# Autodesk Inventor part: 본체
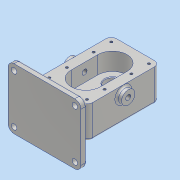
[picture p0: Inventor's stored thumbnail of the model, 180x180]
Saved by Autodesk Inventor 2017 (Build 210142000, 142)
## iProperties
Part Number: 본체
Material: 알루미늄 6061
Document SubType Name: Modeling
Designer: MRC
Density: 2.7 g/cm^3
Appearance: 알루미늄 - 평지
Mass: 1475.56 g
Surface Area: 817.688 cm^2
Volume: 546.504 cm^3
Author: MRC
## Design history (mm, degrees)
sketch "스케치1"
  geometry: L1 (40, -60)-(-40, -60); L2 (-40, -60)-(-40, 60); L3 (-40, 60)-(40, 60); L4 (40, 60)-(40, -60); L5 (40, -60)-(-40, 60); L6 (-40, -60)-(40, 60); 1 further point
  constraints: 12 end point, 2 midpoint, 2 parallel, 1 horizontal, 1 perpendicular
  dimensions: "d0" = 80 distance of L2.end L3.end; "d1" = 120 distance of L1.end L2.end
extrude "돌출1" new body sketch "스케치1" distance "d2" = 14; taper "d4" = 0 deg; dims "d3" = 39, "d5" = 0
sketch "스케치2"
  geometry: L1 (0, 22)-(0, -22); L2 (-24, 22)-(-24, -22); L3 (24, -22)-(24, 22); A1 r 24 centre (0, 22) between (24, 22) and (-24, 22); A2 r 24 centre (0, -22) between (-24, -22) and (24, -22); 2 further points
  constraints: 8 end point, 4 point on circle, 4 tangent, 2 centre point, 2 coincident, 1 midpoint, 1 parallel, 1 vertical
  dimensions: "d6" = 24 radius of A1; "d7" = 92 dimension on A1 A2
extrude "돌출2" cut sketch "스케치2" distance "d8" = 29; taper "d9" = 0 deg
sketch "스케치3"
  geometry: C1 r 12.5 at (0, 22); C2 r 12.5 at (0, -22); A1 r 24 centre (0, -22) between (-24, -22) and (24, -22) reference; A2 r 24 centre (0, 22) between (24, 22) and (-24, 22) reference; 1 further point
  constraints: 2 centre point, 2 coincident
  dimensions: "d10" = 25 diameter of C1; "d11" = 25 diameter of C2
extrude "돌출3" cut sketch "스케치3" distance "d12" = 15; taper "d13" = 0 deg
sketch "스케치4"
  geometry: C1 r 19 at (0, 22); C2 r 12.5 at (0, 22) reference; 1 further point
  constraints: 1 centre point, 1 concentric
  dimensions: "d14" = 38 diameter of C1
extrude "돌출4" join sketch "스케치4" distance "d15" = 17; taper "d16" = 0 deg
hole "구멍1" diameter "d19" = 17; stored, may be unused: countersink angle "d23" = 90 deg, drill point angle "d25" = 118 deg; dims "d17" = 10, "d18" = 10, "d20" = 6, "d21" = 28, "d22" = 7.3, "d24" = 8
sketch "스케치5"
  geometry: L1 (40, -60)-(40, 60) reference; L2 (-31, 51)-(31, 51); L3 (31, 51)-(31, 22); L4 (31, 22)-(31, -22); L5 (31, -22)-(31, -51); L6 (31, -51)-(-31, -51); L7 (-31, -51)-(-31, -22); L8 (-31, -22)-(-31, 22); L9 (-31, 22)-(-31, 51); A1 r 24 centre (0, 22) between (24, 22) and (-24, 22) reference; 3 further points
  constraints: 16 end point, 3 perpendicular, 3 vertical alignment, 2 midpoint, 2 parallel, 1 collinear, 1 horizontal alignment, 1 vertical
  dimensions: "d26" = 102 distance of L6.end L2.start; "d27" = 44 distance of L7.end L8.end; "d28" = 29 distance of L2.start L8.end; "d99" = 29 distance of L2.end L3.end; "d100" = 44 distance of L3.end L4.end; "d101" = 62 distance of L2.end L2.start
hole "구멍2" sketch "스케치5" at (-31, 51), (-31, 22), (-31, -22), (-31, -51), (31, -51), (31, -22), (31, 22), (31, 51) diameter "d29" = 4.134; stored, may be unused: countersink angle "d33" = 90 deg, drill point angle "d35" = 118 deg; dims "d30" = 10, "d31" = 28, "d32" = 7.3, "d34" = 12
sketch "스케치6"
  geometry: C1 r 11 at (14, 60); 1 further point
  constraints: 1 centre point, 1 coincident
  dimensions: "d36" = 22 diameter of C1
extrude "돌출5" join sketch "스케치6" distance "d37" = 8; taper "d38" = 0 deg
hole "구멍3" diameter "d41" = 8.376; stored, may be unused: countersink angle "d45" = 90 deg, drill point angle "d47" = 118 deg; dims "d42" = 20, "d43" = 28, "d44" = 7.3, "d46" = 27.3, "d96" = 10, "d97" = 10
node "작업 평면1"
sketch "스케치7"
  geometry: L1 (-60, 44)-(60, 44); L2 (60, 44)-(60, -56); L3 (60, -56)-(-60, -56); L4 (-60, -56)-(-60, 44); L5 (-60, 44)-(60, -56); L6 (60, 44)-(-60, -56); L7 (-19, -56)-(19, -56) reference; 3 further points
  constraints: 12 end point, 4 midpoint, 2 parallel, 1 horizontal, 1 perpendicular, 1 vertical alignment
  dimensions: "d51" = 120 distance of L2.end L3.end; "d52" = 100 distance of L1.end L2.end
extrude "돌출6" join sketch "스케치7" distance "d53" = 10; taper "d54" = 0 deg
sketch "스케치8"
  geometry: L1 (-65.05, -30.369)-(-80, -39); L2 (-62.591, 3.949)-(-80, 14); L3 (-80, -56)-(-80, 44) reference; L4 (-90, -56)-(-80, -56) reference; L5 (-80, 44)-(-80, -56) reference; 1 further point
  constraints: 4 end point, 2 point on line
  dimensions: "d56" = 60 deg angle of L2 L3; "d57" = 17 distance from line of L4 L1.end; "d58" = 60 deg angle of L3 L1; "d59" = 53 distance of L1.end L2.end
feature "리브1" dims "d60" = 1, "d61" = 48, "d62" = 0, "d63" = 0, "d64" = 1, "d65" = 1
feature "리브2" dims "d66" = 1, "d67" = 48, "d68" = 0, "d69" = 0, "d70" = 1, "d71" = 1
fillet "모깎기1" dims "d72" = 10
sketch "스케치9"
  geometry: C1 r 4.5 at (-50, 46); A1 r 10 centre (-50, 46) between (-50, 56) and (-60, 46) reference; 1 further point
  constraints: 1 centre point, 1 coincident
  dimensions: "d73" = 9 diameter of C1
extrude "돌출7" cut sketch "스케치9" distance "d74" = 10; taper "d75" = 0 deg
fillet "모깎기2" dims "d82" = 9
fillet "모깎기3" dims "d83" = 3
fillet "모깎기4" dims "d84" = 3
chamfer "모따기1" distance "d85" = 1; stored, may be unused: second distance "d86" = 2, angle "d87" = 45 deg
chamfer "모따기2" distance "d88" = 0.7; stored, may be unused: second distance "d89" = 2, angle "d90" = 30 deg
sketch "스케치10"
  geometry: L1 (-50, -44)-(50, -44) reference; L2 (60, -34)-(60, 46) reference; 2 further points
  constraints: 1 other
  dimensions: "d92" = 10 distance from line of L1 point (0, -34); "d93" = 60 distance from line of L2 point (0, -34)
feature "엠보싱1" sketch "스케치10" dims "d0" = 80, "d1" = 120, "d94" = 0.5, "d95" = 0
fillet "모깎기5" dims "d98" = 0.5
chamfer "모따기3" distance "d102" = 1; stored, may be unused: second distance "d103" = 2, angle "d104" = 30 deg
node "솔리드1"
mirror "미러1"
pattern_linear "직사각형 패턴1" dims "d78" = 80, "d81" = 100
